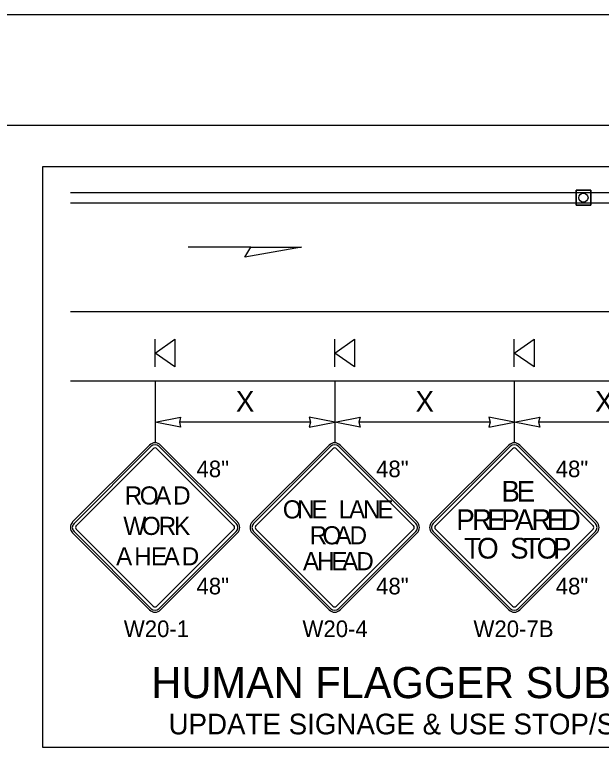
# Model space of a CAD drawing. Extents: x 99999.1 to 100095.7, y 99995 to 100010.7.
# Drawn here: x 100045 to 100047.123, y 100003.48 to 100006.132 of the extents above; entities that cross this region are included whole.
import ezdxf

# ---------------------------------------------------------------- set-up
doc = ezdxf.new("R2010")
doc.units = 0
for name, color, linetype in [('RD_ED_ShoulderPavedEdge', 7, 'Continuous'), ('RD_MK_LineDblYellowCenter', 7, 'Continuous'), ('RD_MK_LineEdgeWhite', 7, 'Continuous'), ('SH_DE_DetailHeading2Text', 7, 'Continuous'), ('TR_SN_ConstructionSigns', 7, 'Continuous'), ('TR_WZ_PortableSignMountBlk-Org', 7, 'Continuous'), ('TR_WZ_TrafficCone', 7, 'Continuous'), ('TR_WZ_WorkZoneDetails', 7, 'Continuous'), ('TR_WZ_WorkZoneTextCurrent', 7, 'Continuous')]:
    doc.layers.add(name, color=color, linetype=linetype)

msp = doc.modelspace()

# ---------------------------------------------------------------- linework, layer by layer
at = {"layer": 'RD_ED_ShoulderPavedEdge'}
for p, q in [((100040.1076, 100005.7323), (100055.6424, 100005.7323)), ((100045.2015, 100004.8073), (100048.9925, 100004.8073))]:
    msp.add_line(p, q, dxfattribs=at)
at = {"layer": 'RD_MK_LineDblYellowCenter'}
for p, q in [((100045.2015, 100005.4886), (100048.0081, 100005.4886)), ((100045.2015, 100005.4511), (100048.0081, 100005.4511))]:
    msp.add_line(p, q, dxfattribs=at)
at = {"layer": 'RD_MK_LineEdgeWhite'}
for p, q in [((100040.1076, 100006.1323), (100055.6424, 100006.1323)), ((100045.2015, 100005.0573), (100048.9925, 100005.0573))]:
    msp.add_line(p, q, dxfattribs=at)
at = {"layer": 'TR_SN_ConstructionSigns'}
for p, q in [((100045.4882, 100004.5741), (100045.2098, 100004.2957)), ((100045.4932, 100004.5691), (100045.2147, 100004.2907)), ((100045.223, 100004.2824), (100045.5015, 100004.5608)), ((100045.5147, 100004.5608), (100045.7931, 100004.2824)), ((100045.8014, 100004.2907), (100045.523, 100004.5691)), ((100045.8064, 100004.2957), (100045.528, 100004.5741)), ((100046.1382, 100004.5741), (100045.8598, 100004.2957)), ((100046.1432, 100004.5691), (100045.8647, 100004.2907)), ((100045.873, 100004.2824), (100046.1515, 100004.5608)), ((100046.1647, 100004.5608), (100046.4431, 100004.2824)), ((100046.4514, 100004.2907), (100046.173, 100004.5691)), ((100046.4564, 100004.2957), (100046.178, 100004.5741)), ((100046.7882, 100004.5741), (100046.5098, 100004.2957)), ((100046.7932, 100004.5691), (100046.5147, 100004.2907)), ((100046.523, 100004.2824), (100046.8015, 100004.5608)), ((100046.8147, 100004.5608), (100047.0931, 100004.2824)), ((100047.1014, 100004.2907), (100046.823, 100004.5691)), ((100047.1064, 100004.2957), (100046.828, 100004.5741)), ((100045.5015, 100003.9907), (100045.223, 100004.2692)), ((100045.7931, 100004.2692), (100045.5147, 100003.9907)), ((100046.1515, 100003.9907), (100045.873, 100004.2692)), ((100046.4431, 100004.2692), (100046.1647, 100003.9907)), ((100046.8015, 100003.9907), (100046.523, 100004.2692)), ((100047.0931, 100004.2692), (100046.8147, 100003.9907)), ((100045.2098, 100004.2559), (100045.4882, 100003.9775)), ((100045.2147, 100004.2609), (100045.4932, 100003.9824)), ((100045.523, 100003.9824), (100045.8014, 100004.2609)), ((100045.528, 100003.9775), (100045.8064, 100004.2559)), ((100045.8598, 100004.2559), (100046.1382, 100003.9775)), ((100045.8647, 100004.2609), (100046.1432, 100003.9824)), ((100046.173, 100003.9824), (100046.4514, 100004.2609)), ((100046.178, 100003.9775), (100046.4564, 100004.2559)), ((100046.5098, 100004.2559), (100046.7882, 100003.9775)), ((100046.5147, 100004.2609), (100046.7932, 100003.9824)), ((100046.823, 100003.9824), (100047.1014, 100004.2609)), ((100046.828, 100003.9775), (100047.1064, 100004.2559))]:
    msp.add_line(p, q, dxfattribs=at)
for centre, radius, start, end in [((100045.5081, 100004.5542), 0.0281, 45, 135), ((100046.1581, 100004.5542), 0.0281, 45, 135), ((100046.8081, 100004.5542), 0.0281, 45, 135), ((100045.5081, 100004.5542), 0.0211, 45, 135), ((100045.5081, 100004.5542), 0.00938, 45, 135), ((100046.1581, 100004.5542), 0.0211, 45, 135), ((100046.1581, 100004.5542), 0.00938, 45, 135), ((100046.8081, 100004.5542), 0.0211, 45, 135), ((100046.8081, 100004.5542), 0.00938, 45, 135), ((100045.2297, 100004.2758), 0.0281, 135, 225), ((100045.2297, 100004.2758), 0.0211, 135, 225), ((100045.7865, 100004.2758), 0.0211, 315, 45), ((100045.7865, 100004.2758), 0.0281, 315, 45), ((100045.8797, 100004.2758), 0.0281, 135, 225), ((100045.8797, 100004.2758), 0.0211, 135, 225), ((100046.4365, 100004.2758), 0.0211, 315, 45), ((100046.4365, 100004.2758), 0.0281, 315, 45), ((100046.5297, 100004.2758), 0.0281, 135, 225), ((100046.5297, 100004.2758), 0.0211, 135, 225), ((100047.0865, 100004.2758), 0.0211, 315, 45), ((100047.0865, 100004.2758), 0.0281, 315, 45), ((100045.2297, 100004.2758), 0.00938, 135, 225), ((100045.7865, 100004.2758), 0.00938, 315, 45), ((100045.8797, 100004.2758), 0.00938, 135, 225), ((100046.4365, 100004.2758), 0.00938, 315, 45), ((100046.5297, 100004.2758), 0.00938, 135, 225), ((100047.0865, 100004.2758), 0.00938, 315, 45), ((100045.5081, 100003.9974), 0.0281, 225, 315), ((100045.5081, 100003.9974), 0.0211, 225, 315), ((100045.5081, 100003.9974), 0.00938, 225, 315), ((100046.1581, 100003.9974), 0.0281, 225, 315), ((100046.1581, 100003.9974), 0.0211, 225, 315), ((100046.1581, 100003.9974), 0.00938, 225, 315), ((100046.8081, 100003.9974), 0.0281, 225, 315), ((100046.8081, 100003.9974), 0.0211, 225, 315), ((100046.8081, 100003.9974), 0.00938, 225, 315)]:
    msp.add_arc(centre, radius, start, end, dxfattribs=at)
at = {"layer": 'TR_WZ_PortableSignMountBlk-Org'}
for p, q in [((100045.5081, 100004.8574), (100045.5081, 100004.9574)), ((100046.1581, 100004.8574), (100046.1581, 100004.9574)), ((100046.8081, 100004.8574), (100046.8081, 100004.9574))]:
    msp.add_line(p, q, dxfattribs=at)
for points in [[(100045.5081, 100004.9073), (100045.5799, 100004.9574), (100045.5799, 100004.8574)], [(100046.1581, 100004.9073), (100046.2299, 100004.9574), (100046.2299, 100004.8574)], [(100046.8081, 100004.9073), (100046.8799, 100004.9574), (100046.8799, 100004.8574)]]:
    msp.add_lwpolyline(points, close=True, dxfattribs=at)
at = {"layer": 'TR_WZ_TrafficCone'}
for points in [[(100047.0848, 100005.4965), (100047.0314, 100005.4965), (100047.0314, 100005.4432), (100047.0848, 100005.4432), (100047.0848, 100005.4965)], [(100047.0848, 100005.4432), (100047.0314, 100005.4432), (100047.0314, 100005.4965), (100047.0848, 100005.4965), (100047.0848, 100005.4432)]]:
    msp.add_lwpolyline(points, dxfattribs=at)
msp.add_circle((100047.0581, 100005.4698), 0.0167, dxfattribs=at)
at = {"layer": 'TR_WZ_WorkZoneDetails'}
for p, q in [((100045.854, 100005.291), (100045.6279, 100005.291)), ((100045.5081, 100004.8073), (100045.5081, 100004.5823)), ((100046.1581, 100004.8073), (100046.1581, 100004.5823)), ((100046.8081, 100004.8073), (100046.8081, 100004.5823)), ((100046.0702, 100004.6573), (100045.596, 100004.6573)), ((100046.7202, 100004.6573), (100046.246, 100004.6573)), ((100047.3702, 100004.6573), (100046.896, 100004.6573))]:
    msp.add_line(p, q, dxfattribs=at)
for points in [[(100046.0382, 100005.291), (100045.8331, 100005.2549), (100045.854, 100005.291)], [(100045.5081, 100004.6573), (100045.6002, 100004.6754), (100045.596, 100004.6573), (100045.6002, 100004.6393)], [(100046.1581, 100004.6573), (100046.0659, 100004.6754), (100046.0702, 100004.6573), (100046.0659, 100004.6393)], [(100046.1581, 100004.6573), (100046.2502, 100004.6754), (100046.246, 100004.6573), (100046.2502, 100004.6393)], [(100046.8081, 100004.6573), (100046.7159, 100004.6754), (100046.7202, 100004.6573), (100046.7159, 100004.6393)], [(100046.8081, 100004.6573), (100046.9002, 100004.6754), (100046.896, 100004.6573), (100046.9002, 100004.6393)]]:
    msp.add_lwpolyline(points, close=True, dxfattribs=at)
at = {"layer": 'TR_WZ_WorkZoneTextCurrent'}
msp.add_lwpolyline([(100045.1015, 100005.5823), (100049.1102, 100005.5823), (100049.1102, 100003.4799), (100045.1015, 100003.4799)], close=True, dxfattribs=at)

# ---------------------------------------------------------------- texts
at = {"layer": 'SH_DE_DetailHeading2Text'}
msp.add_text('HUMAN FLAGGER SUBSTITUTION', height=0.1125, rotation=360, dxfattribs=at).set_placement((100045.4946, 100003.658))
at = {"layer": 'TR_SN_ConstructionSigns'}
for s, p in [('48"', (100045.6579, 100004.4579)), ('48"', (100046.3079, 100004.4579)), ('48"', (100046.9579, 100004.4579)), ('48"', (100045.6579, 100004.0337)), ('48"', (100046.3079, 100004.0337)), ('48"', (100046.9579, 100004.0337)), ('W20-1', (100045.3949, 100003.8792)), ('W20-4', (100046.0415, 100003.8792)), ('W20-7B', (100046.6603, 100003.8792))]:
    msp.add_text(s, height=0.06, rotation=360, dxfattribs=at).set_placement(p)
for s, height, p in [('R', 0.0656, (100045.3982, 100004.359)), ('O', 0.0656, (100045.4526, 100004.359)), ('A', 0.0656, (100045.5078, 100004.359)), ('D', 0.0656, (100045.5734, 100004.359)), ('B', 0.075, (100046.7616, 100004.3695)), ('E', 0.075, (100046.8163, 100004.3695)), ('O', 0.0656, (100045.9704, 100004.3086)), ('N', 0.0656, (100046.0222, 100004.3086)), ('E', 0.0656, (100046.0734, 100004.3086)), ('L', 0.0656, (100046.1725, 100004.3086)), ('A', 0.0656, (100046.2099, 100004.3086)), ('N', 0.0656, (100046.2611, 100004.3086)), ('E', 0.0656, (100046.3123, 100004.3086)), ('P', 0.075, (100046.5981, 100004.2664)), ('R', 0.075, (100046.6551, 100004.2664)), ('E', 0.075, (100046.7098, 100004.2664)), ('P', 0.075, (100046.7608, 100004.2664)), ('A', 0.075, (100046.8118, 100004.2664)), ('R', 0.075, (100046.8703, 100004.2664)), ('E', 0.075, (100046.9251, 100004.2664)), ('D', 0.075, (100046.9761, 100004.2664)), ('W', 0.0656, (100045.3932, 100004.2488)), ('O', 0.0656, (100045.4602, 100004.2488)), ('R', 0.0656, (100045.5212, 100004.2488)), ('K', 0.0656, (100045.577, 100004.2488)), ('R', 0.0656, (100046.0675, 100004.2148)), ('O', 0.0656, (100046.1141, 100004.2148)), ('A', 0.0656, (100046.1607, 100004.2148)), ('D', 0.0656, (100046.2119, 100004.2148)), ('T', 0.075, (100046.6262, 100004.1633)), ('O', 0.075, (100046.6735, 100004.1633)), ('S', 0.075, (100046.7927, 100004.1633)), ('T', 0.075, (100046.8415, 100004.1633)), ('O', 0.075, (100046.8887, 100004.1633)), ('P', 0.075, (100046.948, 100004.1633)), ('A', 0.0656, (100045.367, 100004.1387)), ('H', 0.0656, (100045.4326, 100004.1387)), ('E', 0.0656, (100045.493, 100004.1387)), ('A', 0.0656, (100045.5389, 100004.1387)), ('D', 0.0656, (100045.6046, 100004.1387)), ('A', 0.0656, (100046.0432, 100004.1211)), ('H', 0.0656, (100046.0944, 100004.1211)), ('E', 0.0656, (100046.1456, 100004.1211)), ('A', 0.0656, (100046.185, 100004.1211)), ('D', 0.0656, (100046.2362, 100004.1211))]:
    msp.add_text(s, height=height, dxfattribs=at).set_placement(p)
at = {"layer": 'TR_WZ_WorkZoneTextCurrent'}
for p in [(100045.8005, 100004.6948), (100046.4505, 100004.6948), (100047.1005, 100004.6948)]:
    msp.add_text('X', height=0.075, rotation=360, dxfattribs=at).set_placement(p)
msp.add_text('UPDATE SIGNAGE & USE STOP/SLOW PADDLE', height=0.075, dxfattribs=at).set_placement((100045.5568, 100003.5268))

doc.saveas('drawing.dxf')
